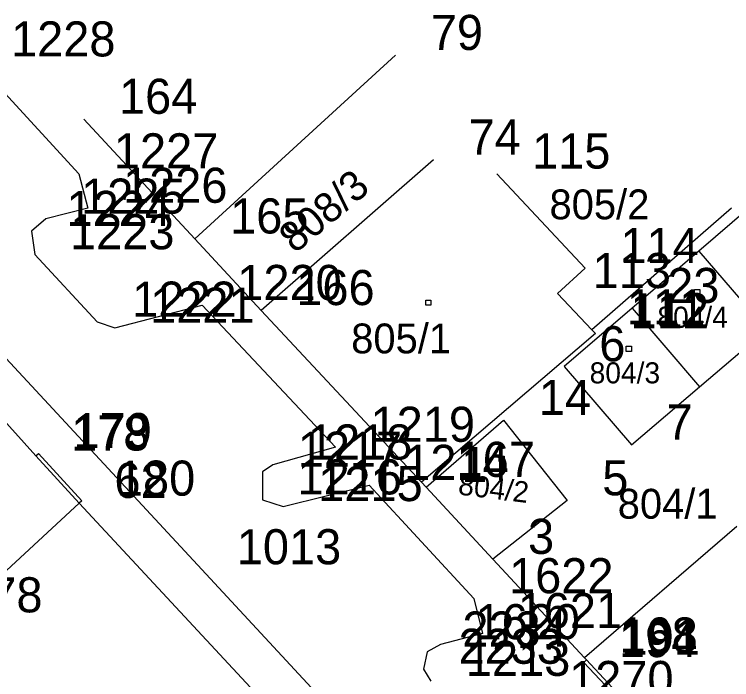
# Model space of a CAD drawing. Extents: x -822293 to -820259, y -1071573 to -1068794.
# Drawn here: x -821588.08 to -821547.22, y -1070015.12 to -1069977.21 of the extents above; entities that cross this region are included whole.
import ezdxf

# ---------------------------------------------------------------- set-up
doc = ezdxf.new("R2010")
doc.units = 0
for name, color, linetype in [('Vrstva 11', 7, 'Continuous'), ('Vrstva 2', 7, 'Continuous'), ('Vrstva 3', 7, 'Continuous'), ('Vrstva 6', 7, 'Continuous'), ('Vrstva 8', 7, 'Continuous'), ('Vrstva 9', 7, 'Continuous')]:
    doc.layers.add(name, color=color, linetype=linetype)

# ---------------------------------------------------------------- blocks, each defined once
blk = doc.blocks.new('Z402')
at = {"layer": 'Vrstva 2'}
for p, q in [((-10, 10), (20, 10)), ((-10, -20), (-10, 10)), ((20, 10), (20, -20)), ((20, -20), (-10, -20))]:
    blk.add_line(p, q, dxfattribs=at)

msp = doc.modelspace()

# ---------------------------------------------------------------- linework, layer by layer
at = {"layer": 'Vrstva 2'}
for p, q in [((-821566.36, -1069979.54), (-821577.79, -1069990)), ((-821584.12, -1069983.18), (-821577.79, -1069990)), ((-821564.21, -1069985.5), (-821574.02, -1069994.08)), ((-821555.56, -1069991.68), (-821560.59, -1069986.3)), ((-821545.21, -1069987.36), (-821549.09, -1069990.7)), ((-821547.23, -1069988.26), (-821555.19, -1069995.18)), ((-821577.79, -1069990), (-821574.02, -1069994.08)), ((-821549.09, -1069990.7), (-821552.89, -1069993.96)), ((-821549.09, -1069990.7), (-821545.25, -1069995.18)), ((-821557.14, -1069993.11), (-821555.56, -1069991.68)), ((-821555.19, -1069995.18), (-821557.14, -1069993.11)), ((-821574.02, -1069994.08), (-821564.89, -1070003.87)), ((-821552.89, -1069993.96), (-821556.76, -1069997.28)), ((-821552.89, -1069993.96), (-821549.05, -1069998.43)), ((-821586.85, -1070002.37), (-821593.78, -1069994.78)), ((-821555.19, -1069995.18), (-821554.98, -1069995.4)), ((-821549.05, -1069998.43), (-821545.25, -1069995.18)), ((-821554.98, -1069995.4), (-821564.89, -1070003.87)), ((-821556.76, -1069997.28), (-821552.93, -1070001.74)), ((-821552.93, -1070001.74), (-821549.05, -1069998.43)), ((-821564.62, -1070004.16), (-821560.21, -1070000.34)), ((-821560.21, -1070000.34), (-821556.59, -1070004.92)), ((-821584.38, -1070005.07), (-821586.85, -1070002.37)), ((-821564.89, -1070003.87), (-821564.62, -1070004.16)), ((-821564.62, -1070004.16), (-821560.82, -1070008.26)), ((-821591.45, -1070011.59), (-821584.38, -1070005.07)), ((-821554.79, -1070036.9), (-821584.38, -1070005.07)), ((-821556.59, -1070004.92), (-821560.82, -1070008.26)), ((-821546.93, -1070006.4), (-821555.61, -1070013.88)), ((-821555.61, -1070013.88), (-821560.82, -1070008.26)), ((-821555.61, -1070013.88), (-821555.49, -1070014)), ((-821555.49, -1070014), (-821552.15, -1070017.56))]:
    msp.add_line(p, q, dxfattribs=at)
at = {"layer": 'Vrstva 3'}
for p, q in [((-821590.27, -1069979.91), (-821584.41, -1069986.29)), ((-821584.41, -1069986.29), (-821583.89, -1069988.25)), ((-821583.89, -1069988.25), (-821586.28, -1069988.87)), ((-821595.91, -1069988.9), (-821577.41, -1070008.85)), ((-821586.28, -1069988.87), (-821587.11, -1069989.57)), ((-821587.11, -1069989.57), (-821586.91, -1069990.9)), ((-821586.91, -1069990.9), (-821583.37, -1069994.74)), ((-821582.35, -1069995.08), (-821577.38, -1069993.79)), ((-821577.38, -1069993.79), (-821569.79, -1070001.87)), ((-821583.37, -1069994.74), (-821582.35, -1069995.08)), ((-821586.85, -1070002.37), (-821586.71, -1070002.23)), ((-821586.71, -1070002.23), (-821584.24, -1070004.94)), ((-821569.79, -1070001.87), (-821573.36, -1070002.88)), ((-821573.36, -1070002.88), (-821573.94, -1070003.29)), ((-821573.94, -1070003.29), (-821573.95, -1070004.87)), ((-821572.77, -1070005.25), (-821567.87, -1070004.04)), ((-821567.87, -1070004.04), (-821561.9, -1070010.5)), ((-821584.24, -1070004.94), (-821584.38, -1070005.07)), ((-821573.95, -1070004.87), (-821572.77, -1070005.25)), ((-821577.41, -1070008.85), (-821565.05, -1070022.16)), ((-821561.9, -1070010.5), (-821561.41, -1070012.49)), ((-821561.41, -1070012.49), (-821563.81, -1070013.12)), ((-821563.81, -1070013.12), (-821564.56, -1070013.54)), ((-821564.56, -1070013.54), (-821564.78, -1070014.52)), ((-821555.49, -1070014), (-821555.64, -1070014.14)), ((-821564.78, -1070014.52), (-821564.36, -1070015.21)), ((-821555.64, -1070014.14), (-821552.3, -1070017.69))]:
    msp.add_line(p, q, dxfattribs=at)
at = {"layer": 'Vrstva 8'}
for p, q in [((-821566.36, -1069979.54), (-821566.36, -1069979.54)), ((-821584.12, -1069983.18), (-821584.12, -1069983.18)), ((-821564.21, -1069985.5), (-821564.21, -1069985.5)), ((-821584.41, -1069986.29), (-821584.41, -1069986.29)), ((-821560.59, -1069986.3), (-821560.59, -1069986.3)), ((-821583.89, -1069988.25), (-821583.89, -1069988.25)), ((-821547.23, -1069988.26), (-821547.23, -1069988.26)), ((-821586.28, -1069988.87), (-821586.28, -1069988.87)), ((-821587.11, -1069989.57), (-821587.11, -1069989.57)), ((-821577.79, -1069990), (-821577.79, -1069990)), ((-821549.09, -1069990.7), (-821549.09, -1069990.7)), ((-821586.91, -1069990.9), (-821586.91, -1069990.9)), ((-821555.56, -1069991.68), (-821555.56, -1069991.68)), ((-821557.14, -1069993.11), (-821557.14, -1069993.11)), ((-821577.38, -1069993.79), (-821577.38, -1069993.79)), ((-821574.02, -1069994.08), (-821574.02, -1069994.08)), ((-821552.89, -1069993.96), (-821552.89, -1069993.96)), ((-821583.37, -1069994.74), (-821583.37, -1069994.74)), ((-821582.35, -1069995.08), (-821582.35, -1069995.08)), ((-821555.19, -1069995.18), (-821555.19, -1069995.18)), ((-821554.98, -1069995.4), (-821554.98, -1069995.4)), ((-821556.76, -1069997.28), (-821556.76, -1069997.28)), ((-821549.05, -1069998.43), (-821549.05, -1069998.43)), ((-821560.21, -1070000.34), (-821560.21, -1070000.34)), ((-821552.93, -1070001.74), (-821552.93, -1070001.74)), ((-821586.71, -1070002.23), (-821586.71, -1070002.23)), ((-821569.79, -1070001.87), (-821569.79, -1070001.87)), ((-821586.85, -1070002.37), (-821586.85, -1070002.37)), ((-821573.36, -1070002.88), (-821573.36, -1070002.88)), ((-821573.94, -1070003.29), (-821573.94, -1070003.29)), ((-821564.89, -1070003.87), (-821564.89, -1070003.87)), ((-821567.87, -1070004.04), (-821567.87, -1070004.04)), ((-821564.62, -1070004.16), (-821564.62, -1070004.16)), ((-821584.38, -1070005.07), (-821584.38, -1070005.07)), ((-821584.24, -1070004.94), (-821584.24, -1070004.94)), ((-821573.95, -1070004.87), (-821573.95, -1070004.87)), ((-821556.59, -1070004.92), (-821556.59, -1070004.92)), ((-821572.77, -1070005.25), (-821572.77, -1070005.25)), ((-821560.82, -1070008.26), (-821560.82, -1070008.26)), ((-821577.41, -1070008.85), (-821577.41, -1070008.85)), ((-821561.9, -1070010.5), (-821561.9, -1070010.5)), ((-821561.41, -1070012.49), (-821561.41, -1070012.49)), ((-821563.81, -1070013.12), (-821563.81, -1070013.12)), ((-821564.56, -1070013.54), (-821564.56, -1070013.54)), ((-821555.61, -1070013.88), (-821555.61, -1070013.88)), ((-821555.49, -1070014), (-821555.49, -1070014)), ((-821564.78, -1070014.52), (-821564.78, -1070014.52)), ((-821555.64, -1070014.14), (-821555.64, -1070014.14))]:
    msp.add_line(p, q, dxfattribs=at)

# ---------------------------------------------------------------- block references
at = {"layer": 'Vrstva 11', "xscale": 0.01, "yscale": 0.01}
for p in [(-821549.23, -1069993), (-821564.55, -1069993.59), (-821553.13, -1069996.22), (-821560.37, -1070002.49)]:
    msp.add_blockref('Z402', p, dxfattribs=at)

# ---------------------------------------------------------------- texts
at = {"layer": 'Vrstva 6'}
for s, height, rotation, p in [('808/3', 1.699, 40, (-821572.093, -1069990.883)), ('804/2', 1.199, 353, (-821562.84, -1070004.57))]:
    msp.add_text(s, height=height, rotation=rotation, dxfattribs=at).set_placement(p)
for s, height, p in [('805/2', 1.7, (-821557.596, -1069988.89)), ('804/4', 1.2, (-821551.45, -1069995.07)), ('805/1', 1.7, (-821568.893, -1069996.53)), ('804/3', 1.2, (-821555.31, -1069998.24)), ('804/1', 1.7, (-821553.71, -1070005.95))]:
    msp.add_text(s, height=height, dxfattribs=at).set_placement(p)
at = {"layer": 'Vrstva 9'}
for s, p in [('79', (-821564.36, -1069979.24)), ('1228', (-821588.27, -1069979.61)), ('164', (-821582.12, -1069982.88)), ('74', (-821562.21, -1069985.2)), ('1227', (-821582.41, -1069985.99)), ('115', (-821558.59, -1069986)), ('1226', (-821581.89, -1069987.95)), ('1225', (-821584.28, -1069988.57)), ('1224', (-821585.11, -1069989.27)), ('165', (-821575.79, -1069989.7)), ('1223', (-821584.91, -1069990.6)), ('114', (-821553.56, -1069991.38)), ('113', (-821555.14, -1069992.81)), ('1220', (-821575.38, -1069993.49)), ('23', (-821550.89, -1069993.66)), ('166', (-821572.02, -1069993.78)), ('1222', (-821581.37, -1069994.44)), ('1221', (-821580.35, -1069994.78)), ('111', (-821553.19, -1069994.88)), ('112', (-821552.98, -1069995.1)), ('6', (-821554.76, -1069996.98)), ('14', (-821558.21, -1070000.04)), ('1219', (-821567.79, -1070001.57)), ('7', (-821550.93, -1070001.44)), ('178', (-821584.85, -1070002.07)), ('179', (-821584.71, -1070001.93)), ('1218', (-821571.36, -1070002.58)), ('1217', (-821571.94, -1070002.99)), ('1214', (-821565.87, -1070003.74)), ('167', (-821562.89, -1070003.57)), ('1', (-821562.62, -1070003.86)), ('180', (-821582.24, -1070004.64)), ('1216', (-821571.95, -1070004.57)), ('5', (-821554.59, -1070004.62)), ('62', (-821582.38, -1070004.77)), ('1215', (-821570.77, -1070004.95)), ('3', (-821558.82, -1070007.96)), ('1013', (-821575.41, -1070008.55)), ('1622', (-821559.9, -1070010.2)), ('78', (-821589.45, -1070011.29)), ('1621', (-821559.41, -1070012.19)), ('1620', (-821561.81, -1070012.82)), ('2234', (-821562.56, -1070013.24)), ('168', (-821553.61, -1070013.58)), ('194', (-821553.64, -1070013.84)), ('191', (-821553.49, -1070013.7)), ('2233', (-821562.78, -1070014.22)), ('1213', (-821562.36, -1070014.91)), ('1270', (-821556.48, -1070016.06))]:
    msp.add_text(s, height=2, dxfattribs=at).set_placement(p)

doc.saveas('drawing.dxf')
